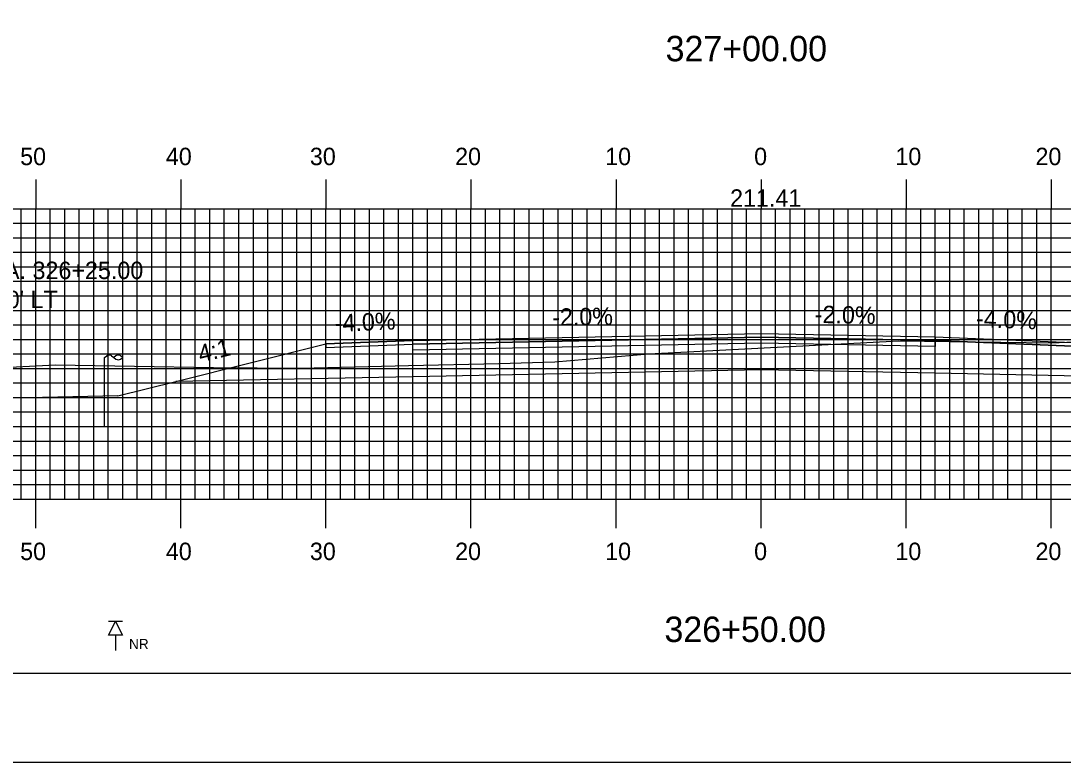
# Model space of a CAD drawing. Extents: x 1821605 to 1821948, y 442591 to 442811.
# Drawn here: x 1821719.7 to 1821791.6, y 442590.5 to 442641.6 of the extents above; entities that cross this region are included whole.
import ezdxf

# ---------------------------------------------------------------- set-up
doc = ezdxf.new("R2010")
doc.units = 0
for name, color, linetype in [('ANNOTATION', 7, 'Continuous'), ('BORDER', 7, 'Continuous'), ('BORING - NO REFUSAL', 7, 'Continuous'), ('D_Drainage_Text', 7, 'Continuous'), ('D_Roadway_Centerline', 7, 'Continuous'), ('D_Roadway_Centerline_Text', 7, 'Continuous'), ('D_Roadway_Edge_Shoulder', 7, 'Continuous'), ('D_Roadway_Edge_TW', 7, 'Continuous'), ('D_Roadway_Pavement', 7, 'Continuous'), ('D_Roadway_SubGrade', 7, 'Continuous'), ('D_Utilities_Pole_Joint', 7, 'Continuous'), ('H_V ANNOTATION', 7, 'Continuous'), ('MAJOR', 7, 'Continuous'), ('MINOR', 7, 'Continuous'), ('PLOT BOUNDARY', 7, 'Continuous'), ('S_Roadway_Centerline', 7, 'Continuous')]:
    doc.layers.add(name, color=color, linetype=linetype)

msp = doc.modelspace()

# ---------------------------------------------------------------- linework, layer by layer
at = {"layer": 'ANNOTATION'}
msp.add_line((1821726.395, 442615.766), (1821630.743, 442613.853), dxfattribs=at)
at = {"layer": 'BORDER'}
msp.add_lwpolyline([(1821621.143, 442596.665), (1821941.143, 442596.665), (1821941.143, 442806.665), (1821621.143, 442806.665)], close=True, dxfattribs=at)
at = {"layer": 'BORING - NO REFUSAL'}
for p, q in [((1821726.723, 442600.245), (1821725.763, 442600.245)), ((1821726.243, 442599.286), (1821726.243, 442598.227))]:
    msp.add_line(p, q, dxfattribs=at)
msp.add_lwpolyline([(1821726.243, 442600.245), (1821726.723, 442599.286), (1821725.763, 442599.286)], close=True, dxfattribs=at)
at = {"layer": 'D_Roadway_Centerline'}
msp.add_lwpolyline([(1821726.395, 442615.766), (1821730.395, 442616.766), (1821740.743, 442619.353), (1821746.743, 442619.593), (1821770.743, 442620.073), (1821782.743, 442619.833), (1821792.743, 442619.433), (1821802.743, 442616.933), (1821806.743, 442615.933), (1821820.81, 442619.45), (1821822.06, 442619.724), (1821823.31, 442619.922), (1821824.56, 442620.044), (1821825.81, 442620.089)], dxfattribs=at)
at = {"layer": 'D_Roadway_Edge_Shoulder'}
for points in [[(1821746.743, 442619.593), (1821740.743, 442619.353), (1821740.743, 442619.103), (1821746.743, 442619.343)], [(1821782.743, 442619.833), (1821792.743, 442619.433), (1821792.743, 442619.183), (1821782.743, 442619.583)]]:
    msp.add_lwpolyline(points, close=True, dxfattribs=at)
at = {"layer": 'D_Roadway_Edge_TW'}
msp.add_lwpolyline([(1821746.743, 442619.343), (1821746.743, 442619.593), (1821770.743, 442620.073), (1821782.743, 442619.833), (1821782.743, 442619.583), (1821770.743, 442619.823)], close=True, dxfattribs=at)
at = {"layer": 'D_Roadway_Pavement'}
msp.add_lwpolyline([(1821746.743, 442618.926), (1821746.743, 442619.343), (1821770.743, 442619.823), (1821782.743, 442619.583), (1821782.743, 442619.166), (1821770.743, 442619.406)], close=True, dxfattribs=at)
at = {"layer": 'D_Roadway_SubGrade'}
msp.add_lwpolyline([(1821746.743, 442617.093), (1821730.395, 442616.766), (1821740.743, 442619.353), (1821740.743, 442619.103), (1821746.743, 442619.343), (1821770.743, 442619.823), (1821782.743, 442619.583), (1821792.743, 442619.183), (1821792.743, 442619.433), (1821802.743, 442616.933), (1821782.743, 442617.333), (1821770.743, 442617.573)], close=True, dxfattribs=at)
at = {"layer": 'D_Utilities_Pole_Joint'}
for p, q in [((1821725.493, 442618.423), (1821725.649, 442618.533)), ((1821725.493, 442613.665), (1821725.493, 442618.423)), ((1821725.962, 442618.533), (1821726.118, 442618.423)), ((1821726.274, 442618.533), (1821726.118, 442618.423)), ((1821726.118, 442618.423), (1821726.274, 442618.312)), ((1821726.743, 442618.423), (1821726.587, 442618.533)), ((1821726.587, 442618.312), (1821726.743, 442618.423)), ((1821726.743, 442613.665), (1821726.743, 442618.423))]:
    msp.add_line(p, q, dxfattribs=at)
for centre, start, end in [((1821725.805, 442618.312), 90, 125.26439), ((1821725.805, 442618.312), 54.73561, 90), ((1821726.43, 442618.312), 90, 125.26439), ((1821726.43, 442618.533), 234.73561, 270), ((1821726.43, 442618.312), 54.73561, 90), ((1821726.43, 442618.533), 270, 305.26439)]:
    msp.add_arc(centre, 0.271, start, end, dxfattribs=at)
at = {"layer": 'MAJOR'}
for p, q in [((1821720.743, 442630.669), (1821720.743, 442628.665)), ((1821730.743, 442630.669), (1821730.743, 442628.665)), ((1821740.743, 442630.669), (1821740.743, 442628.665)), ((1821750.743, 442630.669), (1821750.743, 442628.665)), ((1821760.743, 442630.669), (1821760.743, 442628.665)), ((1821770.743, 442630.669), (1821770.743, 442628.665)), ((1821780.743, 442630.669), (1821780.743, 442628.665)), ((1821790.743, 442630.669), (1821790.743, 442628.665)), ((1821630.743, 442628.665), (1821910.743, 442628.665)), ((1821630.743, 442628.665), (1821910.743, 442628.665)), ((1821720.743, 442608.665), (1821720.743, 442628.665)), ((1821730.743, 442608.665), (1821730.743, 442628.665)), ((1821740.743, 442608.665), (1821740.743, 442628.665)), ((1821750.743, 442608.665), (1821750.743, 442628.665)), ((1821760.743, 442608.665), (1821760.743, 442628.665)), ((1821770.743, 442608.665), (1821770.743, 442628.665)), ((1821780.743, 442608.665), (1821780.743, 442628.665)), ((1821790.743, 442608.665), (1821790.743, 442628.665)), ((1821630.743, 442623.665), (1821910.743, 442623.665)), ((1821630.743, 442618.665), (1821910.743, 442618.665)), ((1821630.743, 442613.665), (1821910.743, 442613.665)), ((1821630.743, 442608.665), (1821910.743, 442608.665)), ((1821630.743, 442608.665), (1821910.743, 442608.665)), ((1821720.743, 442606.661), (1821720.743, 442608.665)), ((1821730.743, 442606.661), (1821730.743, 442608.665)), ((1821740.743, 442606.661), (1821740.743, 442608.665)), ((1821750.743, 442606.661), (1821750.743, 442608.665)), ((1821760.743, 442606.661), (1821760.743, 442608.665)), ((1821770.743, 442606.661), (1821770.743, 442608.665)), ((1821780.743, 442606.661), (1821780.743, 442608.665)), ((1821790.743, 442606.661), (1821790.743, 442608.665))]:
    msp.add_line(p, q, dxfattribs=at)
at = {"layer": 'MINOR'}
for p, q in [((1821719.743, 442608.665), (1821719.743, 442628.665)), ((1821721.743, 442608.665), (1821721.743, 442628.665)), ((1821722.743, 442608.665), (1821722.743, 442628.665)), ((1821723.743, 442608.665), (1821723.743, 442628.665)), ((1821724.743, 442608.665), (1821724.743, 442628.665)), ((1821725.743, 442608.665), (1821725.743, 442628.665)), ((1821726.743, 442608.665), (1821726.743, 442628.665)), ((1821727.743, 442608.665), (1821727.743, 442628.665)), ((1821728.743, 442608.665), (1821728.743, 442628.665)), ((1821729.743, 442608.665), (1821729.743, 442628.665)), ((1821731.743, 442608.665), (1821731.743, 442628.665)), ((1821732.743, 442608.665), (1821732.743, 442628.665)), ((1821733.743, 442608.665), (1821733.743, 442628.665)), ((1821734.743, 442608.665), (1821734.743, 442628.665)), ((1821735.743, 442608.665), (1821735.743, 442628.665)), ((1821736.743, 442608.665), (1821736.743, 442628.665)), ((1821737.743, 442608.665), (1821737.743, 442628.665)), ((1821738.743, 442608.665), (1821738.743, 442628.665)), ((1821739.743, 442608.665), (1821739.743, 442628.665)), ((1821741.743, 442608.665), (1821741.743, 442628.665)), ((1821742.743, 442608.665), (1821742.743, 442628.665)), ((1821743.743, 442608.665), (1821743.743, 442628.665)), ((1821744.743, 442608.665), (1821744.743, 442628.665)), ((1821745.743, 442608.665), (1821745.743, 442628.665)), ((1821746.743, 442608.665), (1821746.743, 442628.665)), ((1821747.743, 442608.665), (1821747.743, 442628.665)), ((1821748.743, 442608.665), (1821748.743, 442628.665)), ((1821749.743, 442608.665), (1821749.743, 442628.665)), ((1821751.743, 442608.665), (1821751.743, 442628.665)), ((1821752.743, 442608.665), (1821752.743, 442628.665)), ((1821753.743, 442608.665), (1821753.743, 442628.665)), ((1821754.743, 442608.665), (1821754.743, 442628.665)), ((1821755.743, 442608.665), (1821755.743, 442628.665)), ((1821756.743, 442608.665), (1821756.743, 442628.665)), ((1821757.743, 442608.665), (1821757.743, 442628.665)), ((1821758.743, 442608.665), (1821758.743, 442628.665)), ((1821759.743, 442608.665), (1821759.743, 442628.665)), ((1821761.743, 442608.665), (1821761.743, 442628.665)), ((1821762.743, 442608.665), (1821762.743, 442628.665)), ((1821763.743, 442608.665), (1821763.743, 442628.665)), ((1821764.743, 442608.665), (1821764.743, 442628.665)), ((1821765.743, 442608.665), (1821765.743, 442628.665)), ((1821766.743, 442608.665), (1821766.743, 442628.665)), ((1821767.743, 442608.665), (1821767.743, 442628.665)), ((1821768.743, 442608.665), (1821768.743, 442628.665)), ((1821769.743, 442608.665), (1821769.743, 442628.665)), ((1821771.743, 442608.665), (1821771.743, 442628.665)), ((1821772.743, 442608.665), (1821772.743, 442628.665)), ((1821773.743, 442608.665), (1821773.743, 442628.665)), ((1821774.743, 442608.665), (1821774.743, 442628.665)), ((1821775.743, 442608.665), (1821775.743, 442628.665)), ((1821776.743, 442608.665), (1821776.743, 442628.665)), ((1821777.743, 442608.665), (1821777.743, 442628.665)), ((1821778.743, 442608.665), (1821778.743, 442628.665)), ((1821779.743, 442608.665), (1821779.743, 442628.665)), ((1821781.743, 442608.665), (1821781.743, 442628.665)), ((1821782.743, 442608.665), (1821782.743, 442628.665)), ((1821783.743, 442608.665), (1821783.743, 442628.665)), ((1821784.743, 442608.665), (1821784.743, 442628.665)), ((1821785.743, 442608.665), (1821785.743, 442628.665)), ((1821786.743, 442608.665), (1821786.743, 442628.665)), ((1821787.743, 442608.665), (1821787.743, 442628.665)), ((1821788.743, 442608.665), (1821788.743, 442628.665)), ((1821789.743, 442608.665), (1821789.743, 442628.665)), ((1821630.743, 442627.665), (1821910.743, 442627.665)), ((1821630.743, 442626.665), (1821910.743, 442626.665)), ((1821630.743, 442625.665), (1821910.743, 442625.665)), ((1821630.743, 442624.665), (1821910.743, 442624.665)), ((1821630.743, 442622.665), (1821910.743, 442622.665)), ((1821630.743, 442621.665), (1821910.743, 442621.665)), ((1821630.743, 442620.665), (1821910.743, 442620.665)), ((1821630.743, 442619.665), (1821910.743, 442619.665)), ((1821630.743, 442617.665), (1821910.743, 442617.665)), ((1821630.743, 442616.665), (1821910.743, 442616.665)), ((1821630.743, 442615.665), (1821910.743, 442615.665)), ((1821630.743, 442614.665), (1821910.743, 442614.665)), ((1821630.743, 442612.665), (1821910.743, 442612.665)), ((1821630.743, 442611.665), (1821910.743, 442611.665)), ((1821630.743, 442610.665), (1821910.743, 442610.665)), ((1821630.743, 442609.665), (1821910.743, 442609.665))]:
    msp.add_line(p, q, dxfattribs=at)
at = {"layer": 'PLOT BOUNDARY'}
msp.add_lwpolyline([(1821604.956, 442590.547), (1821944.956, 442590.547), (1821944.956, 442810.547), (1821604.956, 442810.547)], close=True, dxfattribs=at)
at = {"layer": 'S_Roadway_Centerline'}
msp.add_lwpolyline([(1821713.548, 442617.48), (1821722.117, 442617.916), (1821733.001, 442617.735), (1821739.019, 442617.69), (1821746.432, 442617.869), (1821752.671, 442618.001), (1821756.524, 442618.113), (1821763.007, 442618.664), (1821780.242, 442619.563), (1821790.775, 442619.428), (1821800.044, 442619.833), (1821807.012, 442620.039), (1821809.739, 442620.151), (1821824.605, 442620.067), (1821831.286, 442620.189), (1821840.737, 442620.529), (1821853.23, 442620.607)], dxfattribs=at)

# ---------------------------------------------------------------- texts
at = {"layer": 'ANNOTATION'}
for s, rotation, p in [('-2.0%', 1.14576, (1821756.349, 442620.586)), ('-2.0%', 358.85424, (1821774.429, 442620.8)), ('-4.0%', 357.70939, (1821785.535, 442620.523)), ('-4.0%', 2.29061, (1821741.375, 442620.18)), ('4:1', 14.03624, (1821732.105, 442618.055))]:
    msp.add_text(s, height=1.2, rotation=rotation, dxfattribs=at).set_placement(p)
at = {"layer": 'BORING - NO REFUSAL'}
msp.add_text('NR', height=0.6998, dxfattribs=at).set_placement((1821727.176, 442598.33))
at = {"layer": 'D_Drainage_Text'}
for s, p in [('STA. 326+25.00', (1821716.513, 442623.819)), ("44.0' LT", (1821716.513, 442621.815))]:
    msp.add_text(s, height=1.2, dxfattribs=at).set_placement(p)
at = {"layer": 'D_Roadway_Centerline'}
for s, p in [('C', (1821770.738, 442620.073)), ('L', (1821770.743, 442620.066))]:
    msp.add_text(s, height=0.0146, dxfattribs=at).set_placement(p)
at = {"layer": 'D_Roadway_Centerline_Text'}
msp.add_text('211.41', height=1.2, dxfattribs=at).set_placement((1821768.603, 442628.799))
at = {"layer": 'H_V ANNOTATION'}
for s, height, p in [('327+00.00', 1.75, (1821764.157, 442638.821)), ('50', 1.2, (1821719.672, 442631.665)), ('40', 1.2, (1821729.715, 442631.665)), ('30', 1.2, (1821739.641, 442631.665)), ('20', 1.2, (1821749.651, 442631.665)), ('10', 1.2, (1821759.994, 442631.665)), ('0', 1.2, (1821770.261, 442631.665)), ('10', 1.2, (1821779.994, 442631.665)), ('20', 1.2, (1821789.651, 442631.665)), ('50', 1.2, (1821719.672, 442604.465)), ('40', 1.2, (1821729.715, 442604.465)), ('30', 1.2, (1821739.641, 442604.465)), ('20', 1.2, (1821749.651, 442604.465)), ('10', 1.2, (1821759.994, 442604.465)), ('0', 1.2, (1821770.261, 442604.465)), ('10', 1.2, (1821779.994, 442604.465)), ('20', 1.2, (1821789.651, 442604.465)), ('326+50.00', 1.75, (1821764.079, 442598.821))]:
    msp.add_text(s, height=height, dxfattribs=at).set_placement(p)

doc.saveas('drawing.dxf')
